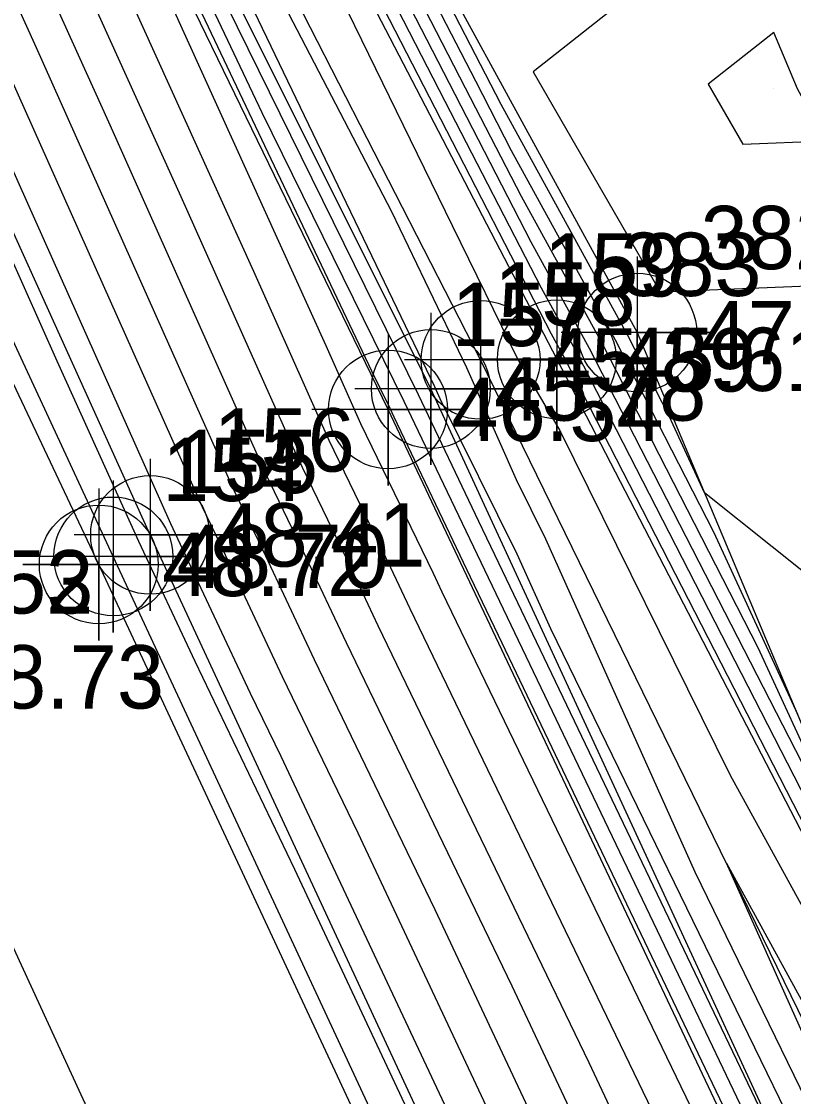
# Model space of a CAD drawing. Extents: x 2090860 to 2091277, y 159470 to 160080.
# Drawn here: x 2091140.32 to 2091170.77, y 159590.22 to 159632.66 of the extents above; entities that cross this region are included whole.
import ezdxf

# ---------------------------------------------------------------- set-up
doc = ezdxf.new("R2010")
doc.units = 0
for name, color, linetype in [('DTM Contours Major', 7, 'Continuous'), ('DTM Contours Minor', 7, 'Continuous'), ('Exist DTM Breakline', 7, 'Continuous'), ('Exist DTM Breakline Cogo Elevation', 7, 'Continuous'), ('Exist DTM Breakline Cogo Number', 7, 'Continuous'), ('Exist DTM Breakline Cogo Point CELL', 7, 'Continuous'), ('Exist DTM Crownline', 7, 'Continuous'), ('Exist DTM Crownline Cogo Elevation', 7, 'Continuous'), ('Exist DTM Crownline Cogo Number', 7, 'Continuous'), ('Exist DTM QL2 LIDAR Elevation Point', 7, 'Continuous'), ('Exist Roads EOP', 7, 'Continuous'), ('Exist Roads EOP Cogo Elevation', 7, 'Continuous'), ('Exist Roads EOP Cogo Number', 7, 'Continuous'), ('Exist Roads EOP Cogo Point CELL', 7, 'Continuous'), ('Exist Roads EOT', 7, 'Continuous'), ('Exist Roads EOT Cogo Elevation', 7, 'Continuous'), ('Exist Roads EOT Cogo Number', 7, 'Continuous'), ('Exist Roads EOT Cogo Point CELL', 7, 'Continuous')]:
    doc.layers.add(name, color=color, linetype=linetype)

msp = doc.modelspace()

# ---------------------------------------------------------------- linework, layer by layer
at = {"layer": 'DTM Contours Major'}
for points in [[(2091113.978, 159781.196), (2091107.95, 159774.542), (2091109.45, 159770.226), (2091108.284, 159761.501), (2091106.966, 159748.316), (2091108.177, 159744.971), (2091106.747, 159743.886), (2091107.873, 159737.592), (2091109.304, 159732.696), (2091114.431, 159718.45), (2091115.247, 159716.067), (2091116.563, 159712.414), (2091119.92, 159704.896), (2091128.935, 159685.065), (2091128.953, 159685.024), (2091132.725, 159677.067), (2091142.133, 159658.086), (2091142.373, 159657.575), (2091143.105, 159656.097), (2091147.178, 159648.664), (2091157.027, 159629.517), (2091160.822, 159622.14), (2091162.224, 159619.585), (2091172.872, 159598.824)], [(2091172.606, 159609.793), (2091167.266, 159614.052), (2091165.877, 159617.077), (2091164.245, 159620.259), (2091159.237, 159629.383), (2091158.623, 159630.578), (2091157.028, 159633.678), (2091144.289, 159656.927), (2091144.155, 159657.198), (2091143.409, 159658.787), (2091141.517, 159662.605), (2091130.506, 159685.833), (2091130.452, 159685.953), (2091126.87, 159693.834)], [(2091171.958, 159584.503), (2091159.156, 159611.268), (2091158.366, 159612.924), (2091155.978, 159617.917), (2091145.488, 159639.267), (2091142.826, 159644.878), (2091142.03, 159646.557), (2091137.674, 159655.374), (2091136.215, 159658.575), (2091132.508, 159667.94), (2091125.612, 159682.971)], [(2091165.757, 159588.524), (2091155.652, 159609.466), (2091154.889, 159611.092), (2091152.463, 159616.122), (2091149.484, 159622.796), (2091140.107, 159643.495), (2091139.218, 159645.485), (2091135.295, 159654.14), (2091133.499, 159658.093), (2091123.124, 159681.571)], [(2091163.429, 159579.673), (2091153.599, 159600.613), (2091150.617, 159606.792), (2091148.169, 159612.011), (2091147.459, 159613.481), (2091138.047, 159634.57), (2091135.191, 159640.875), (2091131.528, 159649.079), (2091130.314, 159651.757), (2091121.742, 159670.624), (2091117.989, 159679.115)]]:
    msp.add_lwpolyline(points, dxfattribs=at)
at = {"layer": 'DTM Contours Minor'}
for points in [[(2091113.452, 159782.082), (2091106.971, 159774.929), (2091107.612, 159773.082), (2091107.114, 159769.349), (2091104.896, 159747.166), (2091105.245, 159746.204), (2091104.833, 159745.892), (2091105.157, 159744.081), (2091107.089, 159737.471), (2091114.009, 159718.241), (2091114.505, 159716.794), (2091116.173, 159712.162), (2091118.183, 159707.661), (2091128.555, 159684.843), (2091128.565, 159684.821), (2091130.527, 159680.683), (2091141.814, 159657.91), (2091141.927, 159657.669), (2091142.809, 159655.89), (2091144.716, 159652.41), (2091156.628, 159629.252), (2091161.218, 159620.33), (2091161.719, 159619.417), (2091174.621, 159594.26)], [(2091129.729, 159685.429), (2091137.121, 159669.836), (2091142.771, 159658.436), (2091143.264, 159657.386), (2091143.697, 159656.512), (2091152.103, 159641.171), (2091157.825, 159630.047), (2091160.03, 159625.762), (2091163.235, 159619.922), (2091169.375, 159607.95), (2091174.599, 159596.569)], [(2091130.118, 159685.631), (2091139.319, 159666.221), (2091143.09, 159658.612), (2091143.709, 159657.292), (2091143.993, 159656.72), (2091154.566, 159637.424), (2091158.224, 159630.313), (2091159.634, 159627.573), (2091163.74, 159620.091), (2091167.626, 159612.514), (2091170.933, 159605.31)], [(2091171.123, 159603.387), (2091162.729, 159619.754), (2091160.426, 159623.951), (2091157.426, 159629.782), (2091149.641, 159644.917), (2091143.401, 159656.305), (2091142.818, 159657.48), (2091142.452, 159658.261), (2091134.923, 159673.452), (2091129.341, 159685.226)], [(2091128.329, 159684.298), (2091134.074, 159672.707), (2091134.907, 159669.238), (2091141.245, 159657.579), (2091142.079, 159655.819), (2091142.914, 159654.108), (2091152.076, 159635.345), (2091157.313, 159624.61), (2091159.9, 159619.312), (2091161.551, 159616.509), (2091168.282, 159602.906), (2091175.112, 159590.435)], [(2091172.908, 159584.624), (2091161.198, 159608.686), (2091159.88, 159611.631), (2091156.831, 159617.768), (2091156.621, 159618.241), (2091146.685, 159638.935), (2091143.428, 159645.208), (2091139.631, 159653.008), (2091138.229, 159655.713), (2091135.085, 159663.655), (2091126.089, 159683.263)], [(2091173.723, 159585.042), (2091166.893, 159599.078), (2091161.009, 159612.222), (2091159.843, 159614.568), (2091157.892, 159618.986), (2091154.934, 159625.148), (2091144.258, 159645.705), (2091142.823, 159648.654), (2091138.936, 159656.155), (2091137.663, 159659.37), (2091126.567, 159683.556)], [(2091160.862, 159578.349), (2091151.097, 159599.184), (2091148.077, 159605.5), (2091147.174, 159607.39), (2091144.949, 159612.13), (2091141.732, 159619.248), (2091132.693, 159639.533), (2091131.752, 159641.619), (2091127.777, 159650.544), (2091122.382, 159662.543), (2091115.863, 159676.89), (2091115.422, 159677.888), (2091115.345, 159678.061), (2091113.296, 159682.58)], [(2091170.957, 159583.654), (2091159.144, 159608.415), (2091158.037, 159610.728), (2091155.026, 159617.04), (2091154.862, 159617.384), (2091154.139, 159618.855), (2091141.984, 159644.478), (2091138.346, 159652.145), (2091136.954, 159654.964), (2091128.801, 159672.849), (2091127.352, 159676.51), (2091124.656, 159682.386)], [(2091171.528, 159583.932), (2091165.551, 159596.459), (2091158.597, 159610.998), (2091156.696, 159614.982), (2091155.42, 159617.651), (2091149.814, 159629.061), (2091142.405, 159644.678), (2091140.188, 159649.351), (2091137.314, 159655.169), (2091132.508, 159665.712), (2091129.93, 159672.225), (2091125.134, 159682.678)], [(2091167.322, 159581.737), (2091162.717, 159591.546), (2091154.394, 159608.797), (2091153.209, 159611.322), (2091151.212, 159615.462), (2091146.624, 159625.74), (2091138.878, 159642.84), (2091137.296, 159646.383), (2091134.05, 159653.544), (2091130.56, 159661.226), (2091121.84, 159680.957)], [(2091166.024, 159581.049), (2091159.678, 159594.568), (2091153.135, 159608.129), (2091151.529, 159611.552), (2091149.961, 159614.801), (2091143.765, 159628.683), (2091137.649, 159642.185), (2091135.373, 159647.282), (2091132.805, 159652.949), (2091127.62, 159664.358), (2091120.556, 159680.343)], [(2091168.797, 159585.501), (2091156.911, 159610.135), (2091156.569, 159610.863), (2091153.713, 159616.782), (2091152.343, 159619.853), (2091141.336, 159644.15), (2091141.141, 159644.586), (2091136.54, 159654.736), (2091136.439, 159654.96), (2091134.42, 159659.528), (2091125.094, 159679.986)], [(2091164.726, 159580.361), (2091156.638, 159597.591), (2091151.876, 159607.46), (2091149.849, 159611.781), (2091148.71, 159614.141), (2091140.906, 159631.627), (2091136.42, 159641.53), (2091133.451, 159648.18), (2091131.56, 159652.353), (2091124.681, 159667.491), (2091119.273, 159679.729)], [(2091162.131, 159578.985), (2091150.559, 159603.635), (2091149.359, 159606.123), (2091146.488, 159612.24), (2091146.209, 159612.821), (2091135.187, 159637.514), (2091133.962, 159640.22), (2091129.606, 159649.977), (2091129.069, 159651.161), (2091118.802, 159673.757), (2091116.705, 159678.502)], [(2091173.426, 159630), (2091170, 159638.18), (2091160.501, 159630.672), (2091165.512, 159621.989), (2091177.521, 159622.479), (2091173.426, 159630)], [(2091170.935, 159630), (2091170, 159632.232), (2091167.408, 159630.183), (2091168.775, 159627.814), (2091172.052, 159627.948), (2091170.935, 159630)], [(2091168.128, 159599.432), (2091174.935, 159587.001), (2091175.418, 159586.04), (2091178.85, 159578.158), (2091180.736, 159574.284), (2091185.931, 159561.894), (2091180.108, 159573.681), (2091178.78, 159576.64), (2091175.038, 159584.354), (2091174.539, 159585.46), (2091172.587, 159589.47), (2091168.128, 159599.432)]]:
    msp.add_lwpolyline(points, dxfattribs=at)
at = {"layer": 'Exist DTM Breakline'}
for points in [[(2091212.183, 159510.746), (2091191.689, 159549.546), (2091174.865, 159585.627), (2091158.431, 159619.302), (2091139.416, 159656.456), (2091124.853, 159687.366), (2091111.104, 159719.28), (2091102.676, 159740.8), (2091098.872, 159752.926), (2091092.871, 159757.669)], [(2091196.63, 159502.872), (2091177.33, 159544.144), (2091161.139, 159578.46), (2091145.393, 159612.39), (2091128.083, 159650.689), (2091112.842, 159682.377), (2091098.521, 159713.445), (2091088.424, 159738.261), (2091087.489, 159747.73)], [(2091104.06, 159746.702), (2091118.019, 159713.353), (2091131.537, 159686.371), (2091144.554, 159657.113), (2091164.611, 159620.381), (2091178.178, 159588.037), (2091195.659, 159551.391), (2091212.727, 159517.77)], [(2091103.084, 159746.105), (2091115.591, 159711.787), (2091128.144, 159684.602), (2091142.549, 159655.707), (2091161.438, 159619.323), (2091177.759, 159587.787), (2091194.782, 159551.104), (2091211.895, 159517.387)], [(2091206.488, 159507.898), (2091187.957, 159548.134), (2091170.754, 159583.555), (2091154.779, 159617.345), (2091136.615, 159654.772), (2091121.985, 159686.47), (2091108.438, 159717.464), (2091100.122, 159738.875)], [(2091208.294, 159508.466), (2091189.147, 159548.511), (2091172.112, 159584.216), (2091156.469, 159618.152), (2091137.831, 159655.463)]]:
    msp.add_lwpolyline(points, dxfattribs=at)
at = {"layer": 'Exist DTM Breakline Cogo Point CELL'}
for points in [[(2091164.611, 159623.381), (2091164.611, 159617.381), (2091164.611, 159620.381), (2091167.611, 159620.381), (2091161.611, 159620.381)], [(2091158.431, 159622.302), (2091158.431, 159616.302), (2091158.431, 159619.302), (2091161.431, 159619.302), (2091155.431, 159619.302)], [(2091161.438, 159622.323), (2091161.438, 159616.323), (2091161.438, 159619.323), (2091164.438, 159619.323), (2091158.438, 159619.323)], [(2091156.469, 159621.152), (2091156.469, 159615.152), (2091156.469, 159618.152), (2091159.469, 159618.152), (2091153.469, 159618.152)], [(2091154.779, 159620.345), (2091154.779, 159614.345), (2091154.779, 159617.345), (2091157.779, 159617.345), (2091151.779, 159617.345)], [(2091145.393, 159615.39), (2091145.393, 159609.39), (2091145.393, 159612.39), (2091148.393, 159612.39), (2091142.393, 159612.39)]]:
    msp.add_lwpolyline(points, dxfattribs=at)
for centre in [(2091164.611, 159620.381), (2091161.438, 159619.323), (2091158.431, 159619.302), (2091156.469, 159618.152), (2091154.779, 159617.345), (2091145.393, 159612.39)]:
    msp.add_circle(centre, 2.344, dxfattribs=at)
at = {"layer": 'Exist DTM Crownline'}
msp.add_lwpolyline([(2091186.231, 159497.374), (2091150.267, 159573.786), (2091135.077, 159606.786), (2091117.269, 159645.439), (2091102.614, 159676.949), (2091088.105, 159708.377), (2091072.916, 159741.265)], dxfattribs=at)
at = {"layer": 'Exist DTM QL2 LIDAR Elevation Point'}
msp.add_line((2091170, 159630), (2091170, 159630), dxfattribs=at)
at = {"layer": 'Exist Roads EOP'}
msp.add_lwpolyline([(2091195.022, 159502.3), (2091175.816, 159543.301), (2091159.602, 159577.847), (2091143.942, 159611.542), (2091126.198, 159649.797), (2091111.241, 159681.734), (2091096.716, 159712.783), (2091082.116, 159745.373)], dxfattribs=at)
at = {"layer": 'Exist Roads EOP Cogo Point CELL'}
msp.add_lwpolyline([(2091143.942, 159614.542), (2091143.942, 159608.542), (2091143.942, 159611.542), (2091146.942, 159611.542), (2091140.942, 159611.542)], dxfattribs=at)
msp.add_circle((2091143.942, 159611.542), 2.344, dxfattribs=at)
at = {"layer": 'Exist Roads EOT'}
msp.add_lwpolyline([(2091194.37, 159502.018), (2091175.119, 159542.803), (2091158.987, 159577.703), (2091143.368, 159611.224), (2091125.349, 159649.375), (2091110.434, 159681.3), (2091096.012, 159712.514), (2091081.141, 159744.981)], dxfattribs=at)
at = {"layer": 'Exist Roads EOT Cogo Point CELL'}
msp.add_lwpolyline([(2091143.368, 159614.224), (2091143.368, 159608.224), (2091143.368, 159611.224), (2091140.368, 159611.224), (2091146.368, 159611.224)], dxfattribs=at)
msp.add_circle((2091143.368, 159611.224), 2.344, dxfattribs=at)

# ---------------------------------------------------------------- texts
at = {"layer": 'Exist DTM Breakline Cogo Elevation'}
for s, p in [('47.18', (2091167.111, 159619.131)), ('45.39', (2091160.931, 159618.052)), ('45.61', (2091163.938, 159618.073)), ('45.78', (2091158.969, 159616.902)), ('46.54', (2091157.279, 159616.095)), ('48.41', (2091147.893, 159611.14))]:
    msp.add_text(s, height=2.5, dxfattribs=at).set_placement(p)
at = {"layer": 'Exist DTM Breakline Cogo Number'}
for s, p in [('382', (2091167.111, 159622.881)), ('159', (2091160.931, 159621.802)), ('383', (2091163.938, 159621.823)), ('158', (2091158.969, 159620.652)), ('157', (2091157.279, 159619.845)), ('156', (2091147.893, 159614.89))]:
    msp.add_text(s, height=2.5, dxfattribs=at).set_placement(p)
at = {"layer": 'Exist DTM Crownline Cogo Elevation'}
msp.add_text('48.73', height=2.5, dxfattribs=at).set_placement((2091137.577, 159605.536))
at = {"layer": 'Exist DTM Crownline Cogo Number'}
msp.add_text('153', height=2.5, dxfattribs=at).set_placement((2091137.577, 159609.286))
at = {"layer": 'Exist Roads EOP Cogo Elevation'}
msp.add_text('48.70', height=2.5, dxfattribs=at).set_placement((2091146.442, 159610.292))
at = {"layer": 'Exist Roads EOP Cogo Number'}
msp.add_text('155', height=2.5, dxfattribs=at).set_placement((2091146.442, 159614.042))
at = {"layer": 'Exist Roads EOT Cogo Elevation'}
for s, p in [('48.72', (2091145.868, 159609.974)), ('48.73', (2091137.577, 159605.536))]:
    msp.add_text(s, height=2.5, dxfattribs=at).set_placement(p)
at = {"layer": 'Exist Roads EOT Cogo Number'}
for s, p in [('154', (2091145.868, 159613.724)), ('152', (2091137.577, 159609.286))]:
    msp.add_text(s, height=2.5, dxfattribs=at).set_placement(p)

doc.saveas('drawing.dxf')
